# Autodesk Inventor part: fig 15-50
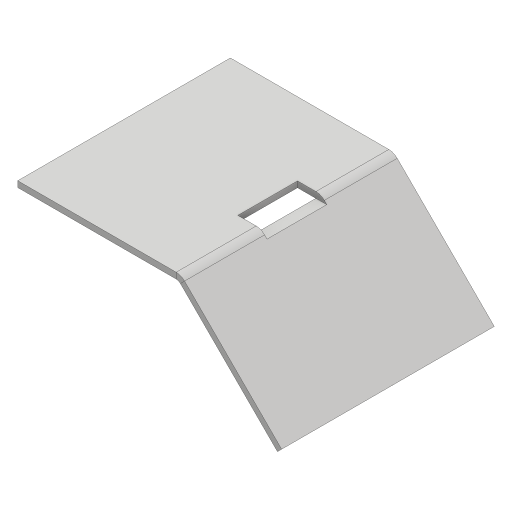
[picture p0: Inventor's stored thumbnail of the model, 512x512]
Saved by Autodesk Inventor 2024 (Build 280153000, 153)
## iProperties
Created: 2015-07
Part Number: fig 15-50
Material: Generic
Document SubType Name: Sheet Metal
Designer: Sandeep
Density: 1 g/cm^3
Sheet Metal Rule: Default_mm
Appearance: Default
Author: Sandeep
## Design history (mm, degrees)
node "Face1"
  sketch "Sketch1"
    geometry: L1 (-9.283, 8.313)-(4.503, 8.313); L2 (4.503, 8.313)-(4.503, -9.63); L3 (4.503, -9.63)-(-9.283, -9.63); L4 (-9.283, -9.63)-(-9.283, 8.313); 1 further point
    constraints: 8 end point, 2 parallel, 1 horizontal, 1 perpendicular
node "Flange1"
sketch "Sketch3"
  geometry: L1 (2.535, 2.162)-(6.789, 2.162); L2 (6.789, 2.162)-(6.789, -2.878); L3 (6.789, -2.878)-(2.535, -2.878); L4 (2.535, -2.878)-(2.535, 2.162); 1 further point
  constraints: 8 end point, 2 parallel, 1 horizontal, 1 perpendicular
cut "Cut1" sketch "Sketch3" dims "d11" = 0.5 (= Thickness), "d12" = 0
body "Solid1"
face "Plate1" dims "d13" = 0.5 (= Thickness)
sketch "Sketch2"
  geometry: L1 (0, -12)-(17.943, -12); L2 (17.943, -12)-(17.943, 0); 1 other entity
  constraints: 4 end point, 4 other
face "Plate2" dims "d1" = 0.5 (= BendReliefWidth), "d2" = 0.25 (= BendReliefDepth), "d3" = 1 (= MinimumRemnant), "d4" = 0.5 (= BendRadius), "d5" = 12, "d6" = 45 deg, "d7" = 0.5 (= BendRadius), "d8" = 2 (= CornerReliefSize), "d9" = 0.5 (= GapSize), "d10" = 0.5 (= JacobiRadiusSize), "d13" = 0.5 (= Thickness), "SeamGap" = 0.01
bend "Bend1" dims "d1" = 0.5 (= BendReliefWidth), "d2" = 0.25 (= BendReliefDepth), "d3" = 1 (= MinimumRemnant), "d4" = 0.5 (= BendRadius), "d5" = 12, "d6" = 45 deg, "d7" = 0.5 (= BendRadius), "d13" = 0.5 (= Thickness), "SeamGap" = 0.01
feature "Corner1" dims "d5" = 12, "d6" = 45 deg, "d8" = 2 (= CornerReliefSize), "d9" = 0.5 (= GapSize), "d10" = 0.5 (= JacobiRadiusSize)
other parameters: "Thickness" = 0.5, "BendRadius" = 0.5 (= Thickness), "BendReliefWidth" = 0.5 (= Thickness), "BendReliefDepth" = 0.25 (= 0.5 x Thickness), "CornerReliefSize" = 2 (= 4 x Thickness), "MinimumRemnant" = 1 (= 2 x Thickness), "TransitionRadius" = 0.5 (= BendRadius), "JacobiRadiusSize" = 0.5 (= BendRadius), "GapSize" = 0.5 (= Thickness), "d0" = 0.5 (= BendRadius)
